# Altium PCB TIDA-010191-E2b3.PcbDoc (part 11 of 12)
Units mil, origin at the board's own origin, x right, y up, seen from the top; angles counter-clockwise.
Board outline 9842.52 x 9842.4 mil, 6 copper layers (Layer 1 - Top Layer, Layer 2 - GND Layer, Layer 3 - Signal, Layer 4 - Signal, Layer 5 - GND, Bottom Layer), stack 59.9 mil thick; 1178 components, 642 nets, 3329 pads, 2967 vias.
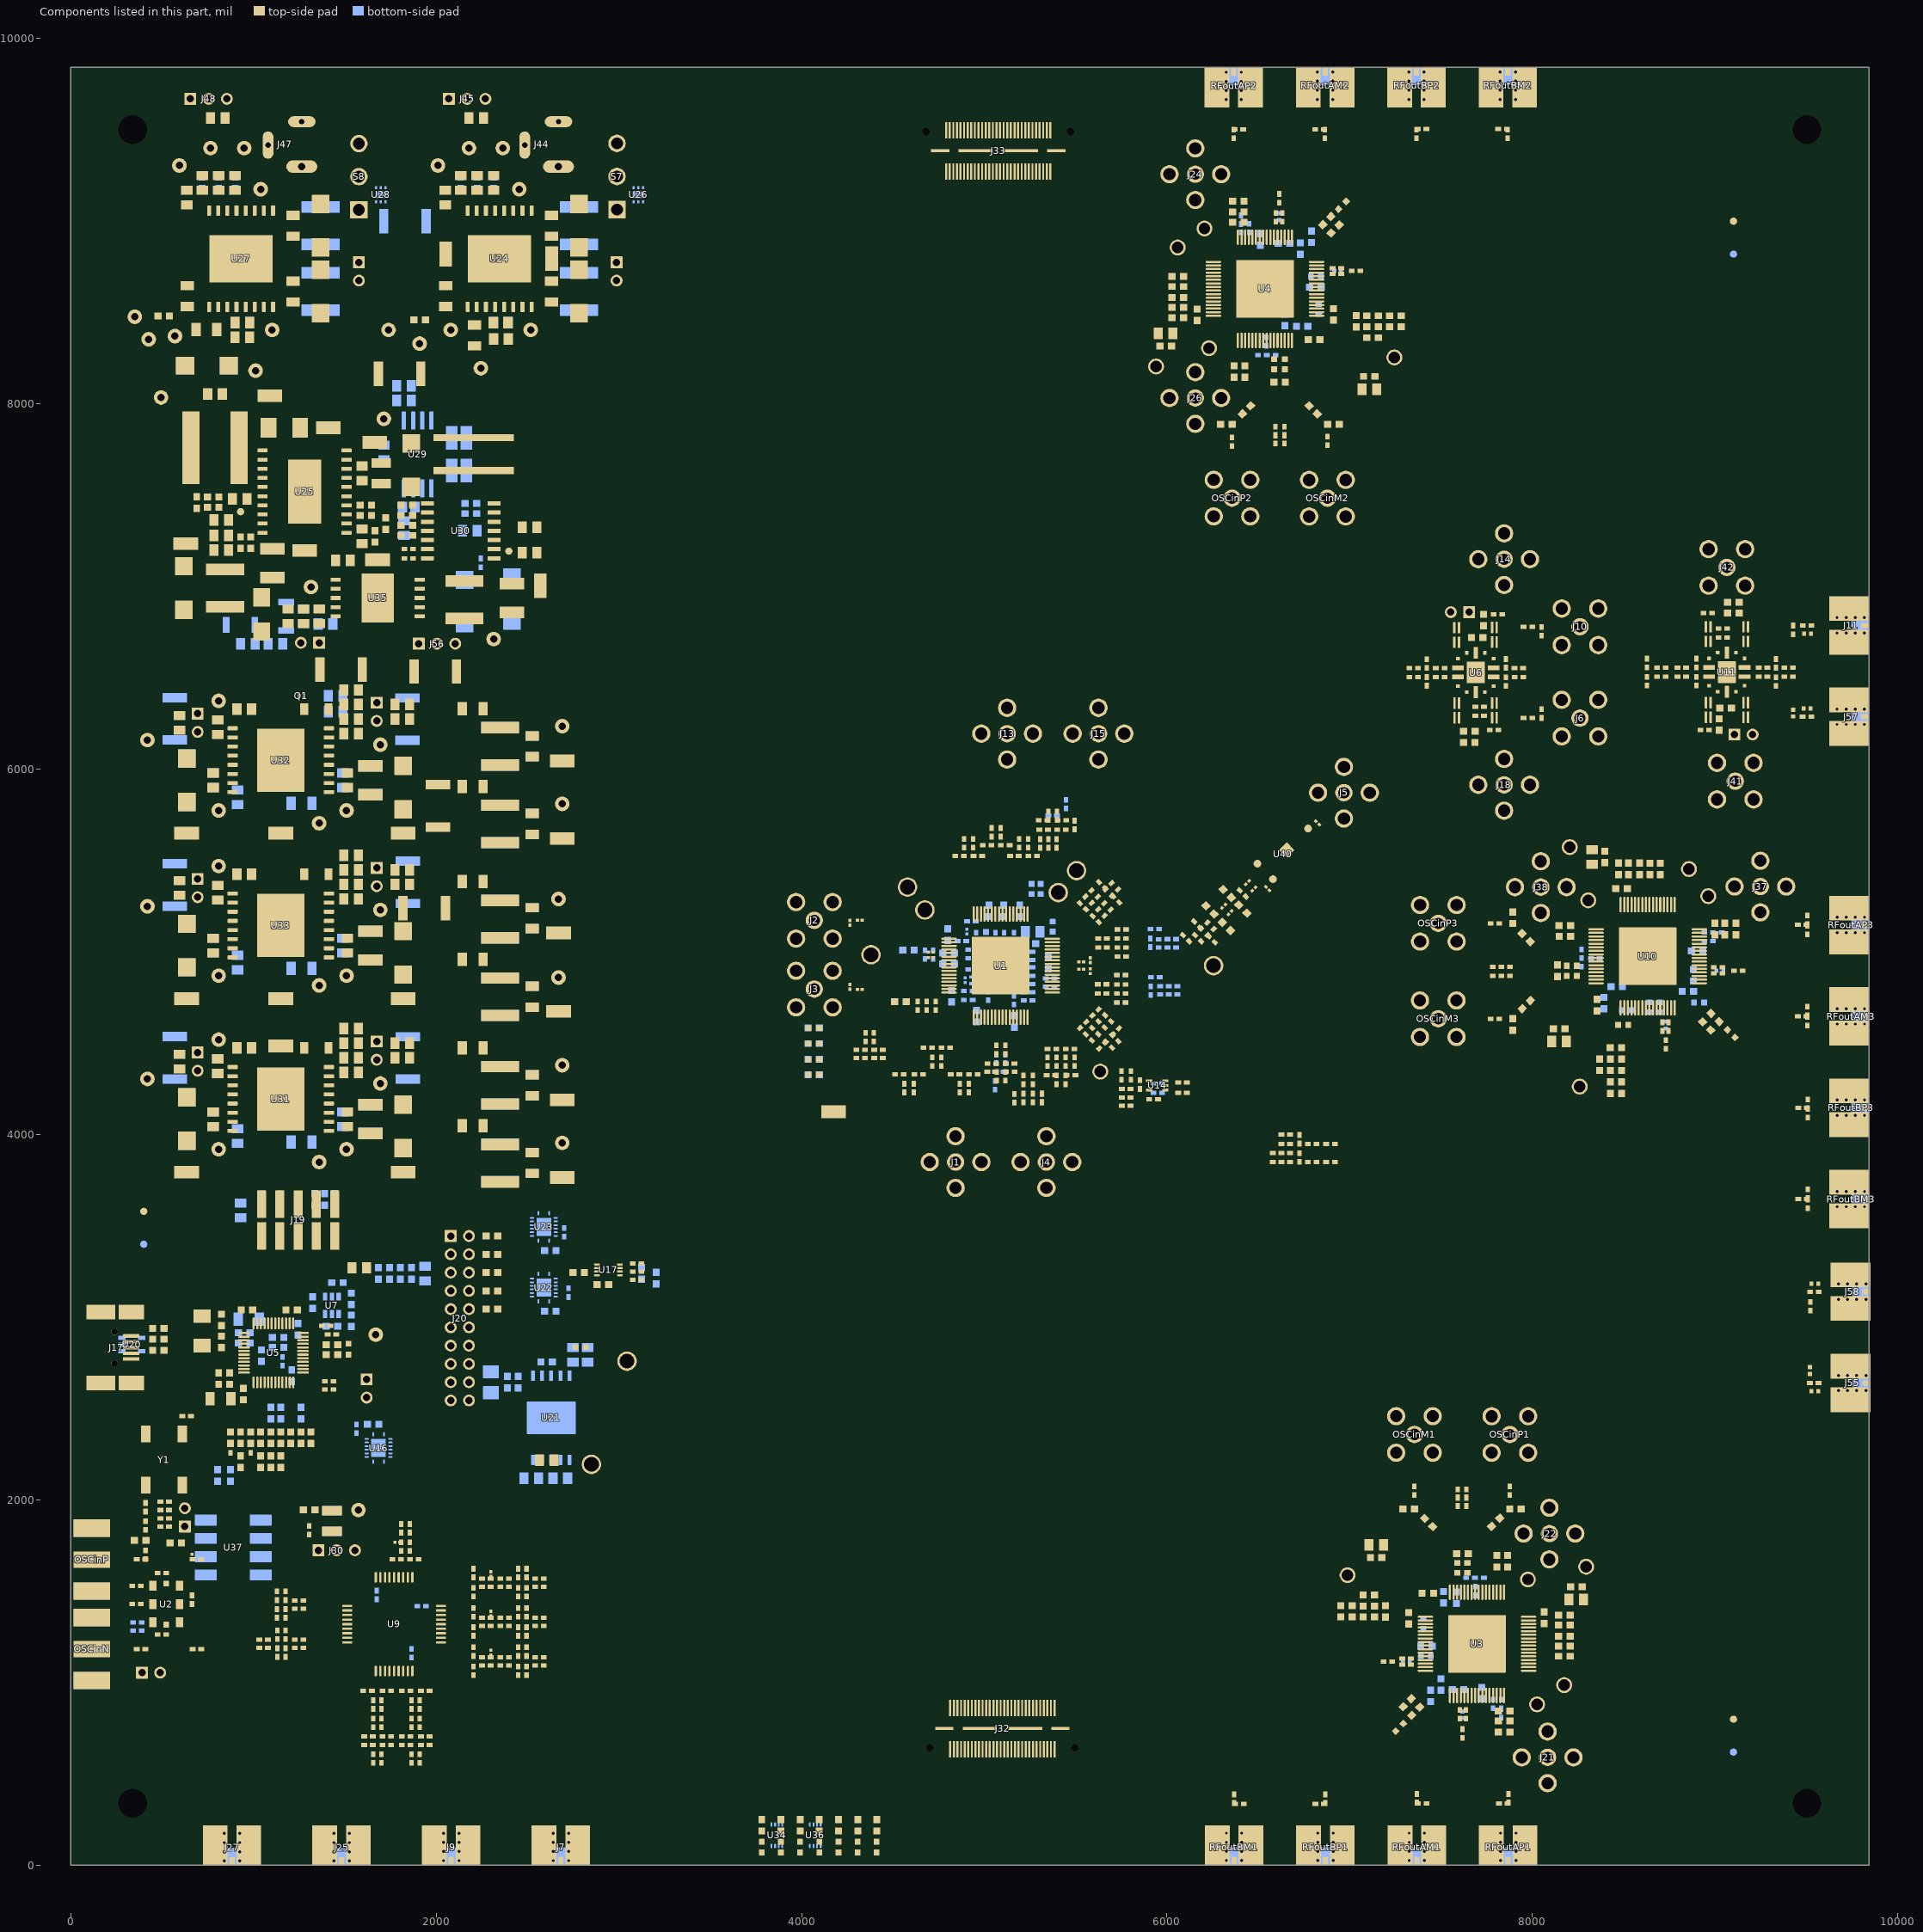
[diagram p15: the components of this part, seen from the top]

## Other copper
Layer 1 - Top Layer:
  region net GND: 7625.94,6467.75 7625.94,6457.75 7580.94,6412.75 7580.94,6233.75 7573.94,6226.75 7538.94,6226.75 7528.94,6236.75 7528.94,6451.75 7544.94,6467.75
  region net P4V5: 7652.94,6455.75 7652.94,6195.75 7643.94,6186.75 7603.94,6186.75 7591.94,6198.75 7591.94,6404.75 7642.94,6455.75
  region net NetC73_2: 7737.94,6604.75 7785.94,6652.75 7785.94,6815.75 7803.94,6833.75 7803.94,6858.75 7771.94,6858.75 7763.94,6850.75 7763.94,6705.75 7726.94,6668.75 7726.94,6604.75
  region net GND: 6211.12,8733.05 6211.12,8784.84 6311.12,8784.84 6321.12,8774.84 6321.12,8739.84 6314.33,8733.05
  region net GND: 6380,8955 6433,8955 6433,8853 6425,8845 6390,8845 6380,8855
  region net GND: 6861,8625 6765,8625 6755,8615 6755,8606 6766,8595 6861,8595
  region net GND: 8021.23,1109.12 8021.23,1058.14 7921.23,1058.14 7911.23,1068.14 7911.23,1103.14 7917.21,1109.12
  region net GND: 8566.43,5301.55 8452.5,5301.55 8305.5,5154.55 8305.5,5060.42 8515.37,5060.42 8566.43,5111.48
  region net GND: 8021.35,1277 8021.35,1390.98 7874.35,1537.98 7778.35,1537.98 7778.35,1329.98 7831.33,1277
  region net GND: 8625,4651.55 8625,4748.05 8615.5,4757.55 8606.5,4757.55 8594.5,4745.55 8594.5,4651.55
  region net GND: 8734.8,5301.43 8780.42,5301.43 8780.42,5196.5 8775.34,5191.43 8740.34,5191.43 8734.8,5196.96
  region net GND: 6211,8565 6211,8452 6358,8305 6452.47,8305 6452.47,8514.53 6402,8565
  region net GND: 960,6370 960,5910 940,5890 855,5890 855,5835 875,5815 875,5730 855,5710 765,5710 745,5730 745,5815 765,5835 855,5835 855,5890 840,5890 815,5915 815,5925 625,5925 565,5865 565,5445 540,5420 540,5360 730,5360 730,5480 780,5530 935,5530 965,5500 965,5010 940,4985 855,4985 855,4930 875,4910 875,4825 855,4805 770,4805 750,4825 750,4910 770,4930 855,4930 855,4985 840,4985 815,5010 815,5020 625,5020 565,4960 565,4495 540,4470 540,4410 730,4410 730,4535 780,4585 925,4585 965,4545 965,4055 945,4035 855,4035 855,3980 875,3960 875,3880 855,3860 765,3860 745,3880 745,3960 763.57,3980 855,3980 855,4035 835,4035 815,4055 815,4070 625,4070 565,4010 565,3749 1895,3749 1895,3980 1770,3980 1680,4070 1480,4070 1480,4015 1495,4000 1540,4000 1595,3945 1595,3875 1515,3795 1328.6,3795 1300,3823.6 1300,4530 1405,4635 1730,4635 1830,4535 1830,4465 1905,4465 1905,4980 1865,5020 1480,5020 1480,4965 1495,4950 1540,4950 1595,4895 1595,4835 1505,4745 1325,4745 1300,4770 1300,5475 1410,5585 1730,5585 1830,5485 1830,5415 1905,5415 1905,5815 1885,5835 1770,5835 1675,5930 1480,5930 1480,5875 1500,5855 1545,5855 1600,5800 1600,5740 1509.53,5649.53 1325.47,5649.53 1300,5675 1300,6370 1257,6370 1257,6420 960,6420
  region net GND: 1986.56,8620 2851.56,8620 2871.56,8640 2871.56,8925 2851.56,8945 1986.56,8945
  region net GND: 560,7315 810,7315 820,7305 820,7165 835,7150 945,7150 965,7170 965,7230 970,7235 1015,7235 1045,7265 1140,7265 1185,7310 1185,7915 1115,7985 820,7985 800,8005 800,8090 810,8100 810,8260 825,8275 940,8275 955,8260 955,8135 980,8110 1140,8110 1300,7950 1555,7950 1665,7840 1910,7840 1935,7815 1935,7735 1925,7725 1830,7725 1735,7630 1460,7630 1375,7545 1375,7340 1405,7310 1535,7310 1540,7305 1540,7285 1530,7275 1475,7275 1340,7140 1060,7140 950,7030 575,7030 545,7060 545,7300
  region net GND: 1500,7170 1510,7180 1545,7180 1560,7195 1560,7257 1568,7265 1695,7265 1755,7205 1755,7135 1780,7110 2345,7110 2360,7125 2555,7125 2605,7075 2605,6935 2595,6925 2145,6925 2080,6990 2055,6990 2020,7025 1845,7025 1805,6985 1805,6870 1945,6730 1945,6655 1925,6635 1605,6635 1580,6660 1580,7030 1500,7110
  region net P5V0: 2460,7480 2523,7417 2523,7151 2532,7142 2578,7142 2640,7080 2640,6940 2600,6900 2140,6900 2075,6965 2050,6965 2015,7000 1875,7000 1860,6985 1860,6890 1875,6875 1940,6875 2065,6750 2065,6485 2100,6450 2750,6450 3000,6700 3000,8440 2855,8585 2385,8585 2360,8560 2360,8175 2300,8115 2200,8115 2080,8235 1885,8235 1835,8185 1835,7940 1915,7860 2025,7750 2410,7750 2460,7700
  region net GND: 634.91,8448 634.91,8368 709.91,8368 709.91,8448
  region net P3V8: 515,7240 515,7530 540,7555 760,7555 780,7575 780,8082 688.5,8173.5 688.5,8247.5 676,8260 610,8260 123,8260 30,8167 30,4200 130,4100 915,4100 935,4120 935,4265 915,4285 570,4285 515,4340 515,4980 585,5050 915,5050 935,5070 935,5215 915,5235 575,5235 515,5295 515,5875 590,5950 915,5950 935,5970 935,6120 915,6140 580,6140 515,6205
  region net NetC156_2: 9118.5,4909.55 9038.5,4909.55 9038.5,4885.55 9118.5,4885.55
  region net GND: 460,2315 460,2410 365,2410 365,2315
  region net NetJ8_1: 585,1880 595,1890 655,1890 665,1880 665,1770 630,1735 595,1735 585,1745
  region net NetC19_2: 520,2105 550,2135 630,2135 660,2105 660,2060 570,1970 570,1745 560,1735 530,1735 520,1745
  region net GND: 5356,9228 5356,9318 5358,9320 5385,9320 5390,9315 5390,9250 5368,9228
  region net GND: 15,940 220,940 220,1080 15,1080
  region net GND: 15,1775.19 220,1775.19 220,1915.19 15,1915.19
  region net GND: 15,1285 220,1285 220,1570 15,1570
  region net GND: 7115,8170 7175,8170 7195,8150 7195,8045 7115,8045
  region net GND: 8391,4822 8293,4822 8276,4839 8276,4849 8282,4855 8387,4855 8391,4851
  region net NetC61_1: 7217.2,1104.31 7297.2,1104.31 7297.2,1128.31 7217.2,1128.31
  region net +3.3VLMK: 4480.61,4652.52 4480.61,4742.52 4490.61,4752.52 4525.61,4752.52 4535.61,4742.52 4535.61,4652.52
  region net GND: 5495.74,765 4705.74,765 4705.74,735 5495.74,735
  region net GND: 4105,4185 4245,4185 4245,4065 4105,4065
  region net NetC173_2: 8741.81,4502.14 8741.81,4582.14 8717.81,4582.14 8717.81,4502.14
  region net GND: 8138.82,4599.38 8078.82,4599.38 8058.82,4579.38 8058.82,4474.38 8138.82,4474.38
  region net P3V3_LMX: 8153.18,4599.38 8213.18,4599.38 8233.18,4579.38 8233.18,4474.38 8153.18,4474.38
  region net GND: 8548.5,4651.55 8548.5,4744.55 8535.5,4757.55 8470.5,4757.55 8470.5,4660.55 8479.5,4651.55
  region net GND: 8418.44,5512.61 8418.44,5427.61 8288.44,5427.61 8288.44,5512.61
  region net P3V3_LMX: 8433.56,5528.61 8443.56,5518.61 8443.56,5468.61 8448.56,5463.61 8488.56,5463.61 8493.56,5468.61 8493.56,5563.61 8438.56,5618.61 8178.56,5618.61 8158.56,5598.61 8158.56,5548.61 8178.56,5528.61
  region net GND: 8955.5,5132.55 8955.5,5081.05 8852,5081.05 8845.5,5087.55 8845.5,5122.55 8855.5,5132.55
  region net GND: 4819.93,816.65 4819.93,924.39 4810.67,933.65 4796.93,933.65 4787.93,924.65 4787.93,816.65
  region net GND: 5378.32,682 5378.32,574.26 5387.58,565 5401.32,565 5410.32,574 5410.32,682
  region net GND: 5253,682 5253,574.26 5243.74,565 5230,565 5221,574 5221,682
  region net GND: 5331.74,682 5331.74,574.26 5322.48,565 5308.74,565 5299.74,574 5299.74,682
  region net GND: 5174.26,682 5174.26,574.26 5165,565 5151.26,565 5142.26,574 5142.26,682
  region net GND: 5095.52,682 5095.52,574.26 5086.26,565 5072.52,565 5063.52,574 5063.52,682
  region net GND: 5016.78,682 5016.78,574.26 5007.52,565 4993.78,565 4984.78,574 4984.78,682
  region net GND: 4938.04,682 4938.04,574.26 4928.78,565 4915.04,565 4906.04,574 4906.04,682
  region net GND: 4859.3,682 4859.3,574.26 4850.04,565 4836.3,565 4827.3,574 4827.3,682
  region net GND: 5338.95,816.65 5338.95,924.39 5348.21,933.65 5361.95,933.65 5370.95,924.65 5370.95,816.65
  region net GND: 5260.21,816.65 5260.21,924.39 5269.47,933.65 5283.21,933.65 5292.21,924.65 5292.21,816.65
  region net GND: 5181.47,816.65 5181.47,924.39 5190.73,933.65 5204.47,933.65 5213.47,924.65 5213.47,816.65
  region net GND: 5102.73,816.65 5102.73,924.39 5111.99,933.65 5125.73,933.65 5134.73,924.65 5134.73,816.65
  region net GND: 5023.99,816.65 5023.99,924.39 5033.25,933.65 5046.99,933.65 5055.99,924.65 5055.99,816.65
  region net GND: 4945.25,816.65 4945.25,924.39 4954.51,933.65 4968.25,933.65 4977.25,924.65 4977.25,816.65
  region net GND: 4866.51,816.65 4866.51,924.39 4875.77,933.65 4889.51,933.65 4898.51,924.65 4898.51,816.65
  region net GND: 7371.35,1218 7467.37,1218 7477.35,1227.98 7477.35,1236.98 7466.33,1248 7371.35,1248
  region net GND: 7371.35,1294.98 7464.35,1294.98 7477.35,1307.98 7477.35,1372.98 7380.35,1372.98 7371.35,1363.98
  region net GND: 7137.82,1665.62 7077.82,1665.62 7057.82,1685.62 7057.82,1790.62 7137.82,1790.62
  region net P3V3_LMX: 7152.18,1665.62 7212.18,1665.62 7232.18,1685.62 7232.18,1790.62 7152.18,1790.62
  region net NetC45_1: 7628,730 7628,810 7604,810 7604,730
  region net GND: 7574.35,1452.98 7574.35,1550.98 7567.35,1557.98 7549.35,1557.98 7542.35,1550.98 7542.35,1452.98
  region net GND: 8232.61,1547.44 8147.61,1547.44 8147.61,1417.44 8232.61,1417.44
  region net P3V3_LMX: 8248.61,1407.44 8238.61,1397.44 8188.61,1397.44 8183.61,1392.44 8183.61,1352.44 8188.61,1347.44 8283.61,1347.44 8338.61,1402.44 8338.61,1662.44 8318.61,1682.44 8268.61,1682.44 8248.61,1662.44
  region net GND: 7852.35,887.98 7800,887.98 7800,990.63 7807.35,997.98 7842.35,997.98 7852.35,987.98
  region net P3V3_LMX: 7100,8170 7040,8170 7020,8150 7020,8045 7100,8045
  region net GND: 6861,8548 6768,8548 6755,8535 6755,8470 6852,8470 6861,8479
  region net NetC189_2: 7027.26,8739.4 6947.26,8739.4 6947.26,8715.4 7027.26,8715.4
  region net P3V3_LMX: 5985,8435 5995,8445 6045,8445 6050,8450 6050,8490 6045,8495 5950,8495 5895,8440 5895,8180 5915,8160 5965,8160 5985,8180
  region net GND: 6000,8295 6085,8295 6085,8425 6000,8425
  region net GND: 6658,8390 6658,8292 6665,8285 6683,8285 6690,8292 6690,8390
  region net +3.3V_CDCM7005: 1270,1895 1295,1920 1295,1965 1270,1990 1185,1990 1170,1975 1170,1910 1185,1895
  region net GND: 1350,1875 1350,1820 1370,1800 1500,1800 1520,1820 1520,1875
  region net C_VCC: 1315,1920 1340,1895 1590,1895 1615,1920 1615,1965 1590,1990 1340,1990 1315,1965
  region net C_VCC: 1838.15,1034.96 1838.15,1103.96 1855.15,1120.96 1870.15,1120.96 1880.15,1110.96 1880.15,1039.96 1875.15,1034.96
  region net C_VCC: 1702,1606 1702,1537 1685,1520 1670,1520 1660,1530 1660,1601 1665,1606
  region net NetC131_2: 6603,9118 6603,9038 6627,9038 6627,9118
  region net NetC75_1: 7726.94,6455.75 7736.94,6455.75 7786.94,6405.75 7786.94,6194.75 7778.94,6186.75 7753.94,6186.75 7743.94,6196.75 7743.94,6226.75 7763.94,6246.75 7763.94,6352.75 7739.94,6376.75 7726.94,6389.75
  region net GND: 7796.94,6194.75 7796.94,6394.75 7803.94,6401.75 7828.94,6401.75 7838.94,6391.75 7838.94,6191.75 7833.94,6186.75 7803.94,6186.75 7796.94,6193.75
  region net P4V5: 7652.94,6604.75 7641.94,6604.75 7591.94,6654.75 7591.94,6813.75 7578.94,6826.75 7533.94,6826.75 7513.94,6846.75 7513.94,6891.75 7528.94,6906.75 7583.94,6906.75 7598.94,6891.75 7598.94,6836.75 7628.94,6806.75 7628.94,6694.75 7652.94,6670.75
  region net GND: 7805.94,6656.75 7796.94,6665.75 7796.94,6807.75 7816.94,6827.75 7816.94,6859.75 7823.94,6866.75 7848.94,6866.75 7853.94,6861.75 7853.94,6666.75 7843.94,6656.75
  region net GND: 7625.94,6592.25 7625.94,6602.25 7580.94,6647.25 7580.94,6807.75 7576.94,6811.75 7543.94,6811.75 7528.94,6796.75 7528.94,6608.25 7544.94,6592.25
  region net GND: 85,2985 105,2965 365,2965 380,2980 478,2980 478,3047 415,3110 105,3110 85,3090
  region net GND: 80,2680 105,2705 259,2705 275,2721 275,2773 284,2782 398,2782 415,2765 415,2590 400,2575 105,2575 80,2600
  region net GND: 1173,2677 1173,2600 1183,2590 1195,2590 1205,2600 1205,2677
  region net GND: 1302,2888 1306,2892 1306,2940 1300,2946 1264,2946 1238,2920 1238,2892 1242,2888
  region net NetJ17_1: 287,2888 378,2888 410,2920 470,2920 470,2960 390,2960 360,2930 298,2930 287,2919
  region net GND: 4804.63,9318.35 4804.63,9210.61 4813.89,9201.35 4827.63,9201.35 4836.63,9210.35 4836.63,9318.35
  region net GND: 4883.37,9318.35 4883.37,9210.61 4892.63,9201.35 4906.37,9201.35 4915.37,9210.35 4915.37,9318.35
  region net GND: 4962.11,9318.35 4962.11,9210.61 4971.37,9201.35 4985.11,9201.35 4994.11,9210.35 4994.11,9318.35
  region net GND: 5040.85,9318.35 5040.85,9210.61 5050.11,9201.35 5063.85,9201.35 5072.85,9210.35 5072.85,9318.35
  region net GND: 5119.59,9318.35 5119.59,9210.61 5128.85,9201.35 5142.59,9201.35 5151.59,9210.35 5151.59,9318.35
  region net GND: 5198.33,9318.35 5198.33,9210.61 5207.59,9201.35 5221.33,9201.35 5230.33,9210.35 5230.33,9318.35
  region net GND: 5277.07,9318.35 5277.07,9210.61 5286.33,9201.35 5300.07,9201.35 5309.07,9210.35 5309.07,9318.35
  region net GND: 4797.42,9453 4797.42,9560.74 4788.16,9570 4774.42,9570 4765.42,9561 4765.42,9453
  region net GND: 4680,9370 5470,9370 5470,9400 4680,9400
  region net GND: 5316.44,9453 5316.44,9560.74 5325.7,9570 5339.44,9570 5348.44,9561 5348.44,9453
  region net GND: 5237.7,9453 5237.7,9560.74 5246.96,9570 5260.7,9570 5269.7,9561 5269.7,9453
  region net GND: 5158.96,9453 5158.96,9560.74 5168.22,9570 5181.96,9570 5190.96,9561 5190.96,9453
  region net GND: 5080.22,9453 5080.22,9560.74 5089.48,9570 5103.22,9570 5112.22,9561 5112.22,9453
  region net GND: 5001.48,9453 5001.48,9560.74 5010.74,9570 5024.48,9570 5033.48,9561 5033.48,9453
  region net GND: 4844,9453 4844,9560.74 4853.26,9570 4867,9570 4876,9561 4876,9453
  region net GND: 4922.74,9453 4922.74,9560.74 4932,9570 4945.74,9570 4954.74,9561 4954.74,9453
  region net VREGIN: 1153,3000 1153,2919 1162,2910 1176,2910 1185,2919 1185,3000
  region net GND: 1114,2934 1114,3014 1160,3060 1200,3060 1200,3020 1160,3020 1145,3005 1145,2934
  region net GND: 995,3000 995,2907 1002,2900 1021,2900 1028,2907 1028,3000
  region net GND: 920,2763 997,2763 1010,2750 1010,2723 998,2711 916,2711 916,2759
  region net GND: 9128,6469.5 9128,6459.5 9173,6414.5 9173,6254 9177,6250 9210,6250 9225,6265 9225,6453.5 9209,6469.5
  region net GND: 9128,6594 9128,6604 9173,6649 9173,6828 9180,6835 9215,6835 9225,6825 9225,6610 9209,6594
  region net GND: 8948,6405 8957,6396 8957,6254 8937,6234 8937,6202 8930,6195 8905,6195 8900,6200 8900,6395 8910,6405
  region net GND: 8957,6867 8957,6667 8950,6660 8925,6660 8915,6670 8915,6870 8920,6875 8950,6875 8957,6868
  region net NetC210_1: 9027,6606 9017,6606 8967,6656 8967,6867 8975,6875 9000,6875 9010,6865 9010,6835 8990,6815 8990,6709 9014,6685 9027,6672
  region net NetC208_2: 9016,6457 8968,6409 8968,6246 8950,6228 8950,6203 8982,6203 8990,6211 8990,6356 9027,6393 9027,6457
  region net P4V5: 9101,6457 9112,6457 9162,6407 9162,6248 9175,6235 9220,6235 9240,6215 9240,6170 9225,6155 9170,6155 9155,6170 9155,6225 9125,6255 9125,6367 9101,6391
  region net P4V5: 9101,6606 9101,6866 9110,6875 9150,6875 9162,6863 9162,6657 9111,6606
  region net GND: 630,6265 540,6265 540,6325 630,6325
  region net P3V3A: 1370,4270.47 1385,4285.47 1605,4285.47 1680,4360.47 1890,4360.47 1920,4390.47 1920,4495.47 1940,4515.47 2170,4515.47 2190,4495.47 2190,4030.47 2170,4010.47 1785,4010.47 1700,4095.47 1385,4095.47 1370,4110.47
  region net GND: 2230,3684.21 2210,3704.21 2210,3804.21 2230,3824.21 2745,3824.21 2765,3804.21 2765,3704.21 2745,3684.21
  region net GND: 2230,4109.21 2210,4129.21 2210,4229.21 2230,4249.21 2745,4249.21 2765,4229.21 2765,4129.21 2745,4109.21
  region net VDDD33: 2210,4067.24 2230,4087.24 2745,4087.24 2765,4067.24 2765,3892.24 2745,3872.24 2235,3872.24 2210,3897.24
  region net +3.3VLMK: 2210,4494.21 2230,4514.21 2745,4514.21 2765,4494.21 2765,4319.21 2745,4299.21 2235,4299.21 2210,4324.21
  region net GND: 2230,4594.21 2210,4614.21 2210,4714.21 2230,4734.21 2745,4734.21 2765,4714.21 2765,4614.21 2745,4594.21
  region net GND: 2230,5019.21 2210,5039.21 2210,5139.21 2230,5159.21 2745,5159.21 2765,5139.21 2765,5039.21 2745,5019.21
  region net +3.3V_CDCM7005: 2210,4979.21 2230,4999.21 2745,4999.21 2765,4979.21 2765,4804.21 2745,4784.21 2235,4784.21 2210,4809.21
  region net +3.3V_VCO: 2210,5404.21 2230,5424.21 2745,5424.21 2765,5404.21 2765,5229.21 2745,5209.21 2235,5209.21 2210,5234.21
  region net NetL28_1: 2170,5730 2190,5710 2190,4935 2170,4915 1985,4915 1965,4935 1965,5300 1925,5340 1925,5710 1945,5730
  region net P3V3C: 1370,5220.47 1385,5235.47 1605,5235.47 1680,5310.47 1924.53,5310.47 1945,5290 1945,5065 1925.47,5045.47 1700,5045.47 1385,5045.47 1370,5060.47
  region net GND: 2230,5540 2210,5560 2210,5660 2230,5680 2745,5680 2765,5660 2765,5560 2745,5540
  region net GND: 2230,5965 2210,5985 2210,6085 2230,6105 2745,6105 2765,6085 2765,5985 2745,5965
  region net +3.3V_LMXRF: 2210,5925 2230,5945 2745,5945 2765,5925 2765,5750 2745,5730 2235,5730 2210,5755
  region net P3V3_LMX: 2210,6350 2230,6370 2745,6370 2765,6350 2765,6165 2745,6145 2230,6145 2210,6165
  region net P3V3B: 1370,6125 1385,6140 1605,6140 1680,6215 1890,6215 1920,6245 1920,6350 1940,6370 2170,6370 2190,6350 2190,5885 2170,5865 1785,5865 1700,5950 1385,5950 1370,5965
  region net NetR545_1: 1561.01,6478.18 1618.91,6478.36 1629.19,6467.02 1906.89,6467.02 1925,6485.13 1925,6585 1897.77,6612.23 1568.35,6612.23 1550,6593.89 1550,6489.2
  region net P4V5: 545,6970 575,7000 955,7000 1065,7110 1345,7110 1415,7180 1470,7180 1480,7170 1480,7090 1500,7070 1500,6945 1480,6925 1240,6925 1225,6910 1225,6850 1220,6845 1000,6845 955,6800 880,6800 845,6765 845,6670 901.6,6613.4 1386.6,6613.4 1415,6585 1415,6475 1390,6450 745,6450 545,6650 545,6830
  region net NetD12_1: 825,7915 870,7960 1095,7960 1140,7915 1140,7575 1095,7530 870,7530 825,7575
  region net GND: 2170,8270 2250,8270 2250,8345 2170,8345
  region net P5V0*: 2405,7700 2430,7675 2430,7520 2405,7495 1740,7495 1725,7480 1475,7480 1455,7500 1455,7595 1475,7615 1750,7615 1835,7700
  region net NetC250_1: 1610,8585 1650,8545 1650,8350 1715,8285 1715,8090 1675,8050 1230,8050 945,8335 945,8560 970,8585
  region net GND: 575,8620 1440,8620 1460,8640 1460,8925 1440,8945 575,8945
  region net GND: 932,9225 778,9225 778,9278 785,9285 785,9330 932,9330
  region net GND: 685,9225 752,9225 752,9278 745,9285 745,9330 685,9330
  region net VIN_P5V0_Redundant: 600,9115 600,9020 610,9010 660,9010 670,9020 670,9115
  region net VIN_P5V0_Redundant: 820,9530 918.31,9530 930,9541.69 930,9588.31 918.31,9600 820,9600
  region net NetJ47_1: 1175,9230 1215,9190 1605,9190 1645,9230 1645,9320 1605,9360 1215,9360 1175,9320
  region net VIN_P5V0_Redundant: 1640,9115 1595,9160 1190,9160 1120,9230 1015,9230 945,9160 945,9015 985,8975 1450,8975 1485,8940 1485,8780 1525,8740 1735,8740 1775,8780 1775,9075 1735,9115
  region net VIN_P5V0: 2235,9530 2333.31,9530 2345,9541.69 2345,9588.31 2333.31,9600 2235,9600
  region net VIN_P5V0: 2015,9115 2015,9020 2025,9010 2075,9010 2085,9020 2085,9115
  region net GND: 2347,9225 2193,9225 2193,9278 2200,9285 2200,9330 2347,9330
  region net GND: 2100,9225 2167,9225 2167,9278 2160,9285 2160,9330 2100,9330
  region net VIN_P5V0: 3055,9115 3010,9160 2605,9160 2535,9230 2430,9230 2360,9160 2360,9015 2400,8975 2865,8975 2900,8940 2900,8780 2940,8740 3150,8740 3190,8780 3190,9075 3150,9115
  region net NetJ44_1: 2580,9230 2620,9190 3010,9190 3050,9230 3050,9320 3010,9360 2620,9360 2580,9320
  text "TOP LAYER" at -232.05,-1884.88 h60
Layer 2 - GND Layer:
  pour cut-out: 420,1285 620,1285 620,1575 425,1575 420,1570
  text "GND Layer" at -204.91,-1899.88 h60
Layer 4 - Signal:
  pour cut-out: 420,1285 620,1285 620,1575 425,1575 420,1570
  text "Signal Layer2" at -214.91,-1899.88 h60
Layer 3 - Signal:
  text "Signal Layer1" at -224.91,-1889.88 h60
Layer 5 - GND:
  text "PWR Layer" at -194.91,-1889.88 h60
Bottom Layer:
  region net GND: 962.03,4145.47 1022,4082.59 1022,4020.47 1298,4020.47 1298,4536.14 962.03,4536.14
  region net GND: 962.03,5095.47 1022,5032.59 1022,4970.47 1298,4970.47 1298,5507.97 962.03,5507.97
  region net GND: 962.03,6000 1022,5937.12 1022,5875 1298,5875 1298,6418.21 962.03,6418.21
  region net P3V3C: 1455,5045.47 1926.26,5045.47 1946,5065.21 1946,5300.47 1590,5300.47 1455,5165.47
  region net P3V8: 552,8143 552,8271 689,8271 689,8143
  region net GND: 940,8272 940,8149 803,8149 803,8272
  region net GND: 973.07,5834.85 973.07,5781.62 966.3,5774.85 881.3,5774.85 881.3,5834.85
  region net GND: 973.18,4930.32 973.18,4877.2 966.3,4870.32 881.3,4870.32 881.3,4930.32
  region net GND: 973.6,3980.32 973.6,3927.63 927.94,3881.97 881.3,3881.97 881.3,3980.32
  region net GND: 15,940 220,940 220,1080 15,1080
  region net GND: 15,1775.19 220,1775.19 220,1915.19 15,1915.19
  region net GND: 15,1285 220,1285 220,1570 15,1570
  region net GND: 565,3753.46 705.11,3753.46 705,3905.47 795,3995.47 854.55,3995.47 854.55,4023.64 812.61,4070.47 625,4070.47 565,4010.47
  region net GND: 1550,3995.47 1575,3970.47 1710,3970.47 1710,4040.47 1690,4060.47 1550,4060.47
  region net GND: 1550,4945.47 1575,4920.47 1710,4920.47 1710,4990.47 1690,5010.47 1550,5010.47
  region net GND: 565,4855.47 705,4855.47 795,4945.47 820,4945.47 820,5015.47 815,5020.47 625,5020.47 565,4960.47
  region net GND: 1550,5850 1647.66,5700.79 1905,5700.79 1905,5915 1550,5915
  region net GND: 565,5760 705,5760 795,5850 820,5850 820,5920 815,5925 625,5925 565,5865
  region net GND: 2055,7080 2055,7015 2125,6945 2530,6945 2530,7080 2485,7125 2100,7125
  region net GND: 1170,8930 1475,8930 1475,8660 1170,8660
  region net GND: 2585,8930 2890,8930 2890,8660 2585,8660
  region net GND: 5235.5,5018.95 5241.59,5025.04 5241.59,5066.29 5245.26,5069.85 5260,5084.59 5260,5139.99 5256.09,5144 5198.84,5144 5194.17,5139.33 5194.17,5088.72 5186.39,5081.38 4928.37,5081.38 4920.51,5089.24 4920.51,5103.03 4916.04,5107.5 4889.1,5107.5 4884.82,5103.22 4884.82,5048.07 4887.85,5045 4932.03,5045 4944.28,5032.75 4944.28,4815.82 4936.5,4808.04 4924.24,4808.04 4924.24,4807.43 4920.26,4803.45 4920.26,4791.8 4920.26,4771.08 4920.06,4725.24 4924.55,4720.75 4952.32,4720.75 4961.3,4729.74 4961.3,4759.34 4966.2,4765 5040,4765 5062.09,4742.91 5179.98,4742.91 5191.48,4731.62 5191.48,4730 5199.77,4721.71 5231.04,4721.71 5235.5,4726.17 5235.5,4760.5
  region net GND: 8621,4705 8601,4725 8601,4755 8606,4760 8641,4760 8661,4740 8661,4710 8656,4705
  region net GND: 1350,1875 1350,1820 1370,1800 1500,1800 1520,1820 1520,1875
  region net C_VCC: 1350,1895 1350,1950 1370,1970 1500,1970 1520,1950 1520,1895
  region net GND: 7480,1188.33 7471.54,1179.87 7431.54,1179.87 7426.54,1184.87 7426.54,1219.87 7451.67,1245 7470,1245 7480,1235
  region net GND: 6755,8655 6760,8660 6800,8660 6805,8655 6805,8620 6785,8600 6760,8600 6755,8605
  region net P5V0: 2675,8570 2870,8570 2890,8550 2890,8475 2675,8475
  region net GND: 1645,3215 1660,3230 1980,3230 1995,3215 1995,3180 1980,3165 1660,3165 1645,3180
  region net GND: 2265,2635 2250,2620 2250,2545 2265,2530 2420,2530 2470,2580 2470,2635
  region net VREGIN: 2545,2655 2540,2650 2265,2650 2255,2660 2255,2750 2265,2760 2490,2760 2545,2705
  region net VDDD33: 1635,3240 1645,3250 1970,3250 1980,3260 1980,3350 1970,3360 1610,3360 1570,3320 1570,3260 1590,3240
  region net P3V3A: 1455,4095.47 1815,4095.47 1915,4195.47 1915,4350.47 1590,4350.47 1455,4215.47
  region net NetR502_1: 705,4508.98 779.53,4583.5 1700.47,4583.5 1775,4508.98 1915,4508.98 1925,4518.98 1925,4623.98 1801.98,4747 633.02,4747 480,4593.98 480,4528.98 500,4508.98
  region net P3V8: 360,4365.47 605,4365.47 670,4300 735,4300 755,4320 755,4345 775,4365.47 835,4365.47 855,4345 855,4095.47 845,4095.47 815,4095.47 520,4095.47 360,4255.47
  region net P3V8: 360,5315.47 605,5315.47 815,5105.47 815,5045.47 520,5045.47 360,5205.47
  region net NetR526_1: 705,5455.47 779.53,5530 1700.47,5530 1775,5455.47 1915,5455.47 1925,5465.47 1925,5570.47 1845.95,5649.53 589.05,5649.53 480,5540.47 480,5475.47 500,5455.47
  region net GND: 2570,3815.79 2570,3685.79 2235,3685.79 2235,3815.79
  region net GND: 2570,4240.79 2570,4110.79 2235,4110.79 2235,4240.79
  region net VDDD33: 2570,3872.24 2570,4002.24 2235,4002.24 2235,3872.24
  region net +3.3VLMK: 2570,4299.21 2570,4429.21 2235,4429.21 2235,4299.21
  region net +3.3V_CDCM7005: 2570,4784.21 2570,4914.21 2235,4914.21 2235,4784.21
  region net +3.3V_VCO: 2570,5209.21 2570,5339.21 2235,5339.21 2235,5209.21
  region net +3.3V_LMXRF: 2570,5730 2570,5860 2235,5860 2235,5730
  region net P3V3B: 1455,5950 1815,5950 1915,6050 1915,6205 1790,6205 1765,6180 1565,6180 1455,6070
  region net P3V8: 360,6220 605,6220 815,6010 815,5950 520,5950 360,6110
  region net GND: 2570,4725.79 2570,4595.79 2235,4595.79 2235,4725.79
  region net GND: 2570,5150.79 2570,5020.79 2235,5020.79 2235,5150.79
  region net GND: 2570,5671.57 2570,5541.57 2235,5541.57 2235,5671.57
  region net GND: 2570,6096.57 2570,5966.57 2235,5966.57 2235,6096.57
  region net P3V3_LMX: 2570,6155 2570,6285 2235,6285 2235,6155
  region net NetR514_1: 702.5,6368.43 787.5,6453.43 1687.5,6453.43 1772.5,6368.43 1912.5,6368.43 1922.5,6378.43 1922.5,6483.43 1792.5,6613.43 637.5,6613.43 477.5,6453.43 477.5,6388.43 497.5,6368.43
  region net P5V0: 2065,6650 2065,6865 2490,6865 2490,6650
  region net GND: 830,6835 885,6835 965,6755 965,6650 900,6650 830,6720
  region net GND: 2175,7260 2095,7260 2095,7350 2175,7350
  region net GND: 1735,8135 1810,8135 1810,7985 1750,7985 1735,8000
  region net GND: 2120,7805 2120,7645 2050,7645 2050,7805
  region net GND: 685,9220 930,9220 930,9330 685,9330
  region net GND: 1660,9174 1740,9174 1740,9220 1660,9220
  region net GND: 2100,9220 2345,9220 2345,9330 2100,9330
  region net GND: 3070,9174 3150,9174 3150,9220 3070,9220
  region net VIN_P5V0: 3051,9116 3149,9116 3170,9095 3051,9095
  text "BOTTOM LAYER" at -231.28,-1903.37 h60

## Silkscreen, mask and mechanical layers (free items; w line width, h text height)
Top Overlay:
  text "P5V0" at 1060,8279.88 h41.77
  text "P5V0" at 2475,8255 h41.77
  text "P3V8" at 445,8145 h41.77
  text "P4V5" at 1275,7065 h41.77
  text "P5V0" at 2275,6565 h41.77
  text "P3V3_LMK" at 2770,6225 h41.77
  text "P3V3B" at 1775,6085 h41.77
  text "P3V8" at 380,6070 h41.77
  text "+3.3V_LMXRF" at 2770,5805 h41.77
  text "+3.3V_VCO" at 2735,5285 h41.77
  text "P3V3C" at 1515,5180.47 h41.77
  text "P3V8" at 375,5160 h41.77
  text "+3.3V_CDCM7005" at 2740,4855 h41.77
  text "+3.3VLMK" at 2770,4370 h41.77
  text "P3V3A" at 1770,4238.07 h41.77
  text "P3V8" at 380,4215 h41.77
  text "VDDD33" at 2780,3945 h41.77
  text "TOP OVERLAY" at -231.28,-1903.37 h50
Bottom Overlay:
  text "BOTTOM OVERLAY" at -117.05,-1916.88 h50
Top Paste:
  text "TOP PASTE" at -231.28,-1903.37 h60
Bottom Paste:
  text "BOTTOM PASTE" at -231.28,-1903.37 h60
Top Solder:
  text "TOP SOLDER" at -231.28,-1903.37 h60
Bottom Solder:
  text "BOTTOM SOLDER" at -231.28,-1903.37 h60
Drill Guide:
  text ".Layer_Name" at -231.28,-1903.37 h60
M1 Board Outline:
  the board outline again, w10
M2 Board Dimensions:
  rectangle: -683.78,-1455.38 -308.78,-1330.38
  rectangle: -808.78,-1330.38 -683.78,-1205.38
  lines w7: -808.78,-1330.38 191.22,-1330.38 ; -683.78,-1455.38 -683.78,-1205.38 ; -558.78,-1455.38 -558.78,-1205.38 ; -308.78,-1455.38 -308.78,-1205.38 ; -58.78,-1455.38 -58.78,-1205.38 ; -808.78,-1455.38 -808.78,-1205.38 191.22,-1205.38 191.22,-1455.38 -808.78,-1455.38
  lines w10: -808.78,-1520.38 -808.78,-1500.38 ; -748.78,-1530.38 -808.78,-1510.38 ; -748.78,-1490.38 -808.78,-1510.38 ; -584.69,-1510.38 -808.78,-1510.38 ; -32.86,-1510.38 191.22,-1510.38 ; 131.22,-1530.38 191.22,-1510.38 ; 131.22,-1490.38 191.22,-1510.38 ; 191.22,-1520.38 191.22,-1500.38
  text "1000 (mil)" at -574.69,-1546.37 h60
M3 3D STEP Top:
  text ".Layer_Name" at -231.28,-1903.37 h60
M4 3D STEP Bottom:
  text ".Layer_Name" at -231.28,-1903.37 h60
M5 Assembly Top:
  lines w10: -1100.28,-1975.05 5499.73,-1975.05 ; -1100.28,-1771.71 5501.73,-1771.71 ; -1100.28,-1568.38 -1100.28,-2178.38 2904.72,-2178.38 5501.73,-2178.38 5501.73,-1568.38 -1099.78,-1568.38 -1099.78,-2178.38 475.72,-2178.38 ; 1364.72,-2178.38 1364.72,-1568.38 ; 2631.72,-1771.71 2631.72,-1568.38 ; 3471.72,-1771.71 3471.72,-1568.38 ; 4093.72,-2184.88 4093.72,-1982.05
  text "COMPONENTS MARKED 'DNP' SHOULD NOT BE POPULATED." at 345.22,-1363.38 h25
  text "ASSEMBLY VARIANT:" at 344.72,-1478.88 h25
  text ".VariantName" at 1380.72,-1478.88 h25
  text "E3" at 3066.95,-1693.88 h25
  text "PCB VIEWED FROM TOP SIDE" at -1036.78,-1700.55 h25
  text "BOARD #:" at 1439.72,-1700.55 h25
  text "'.PRJ_Number'" at 1985.22,-1700.55 h25
  text "REV:" at 2829.72,-1700.55 h25
  text "SVN REV:" at 3667.72,-1700.55 h25
  text "010131" at 1760.82,-1895.68 h25
  text "ASSEMBLY TOP" at -225.05,-1897.88 h25
  text "TID #:" at 1421.99,-1901.01 h25
  text "IGNORE ->" at -1036.78,-1903.37 h25
  text "PLOT NAME =" at -1036.78,-2109.22 h25
  text ".plot_File_Name" at -231.28,-2109.22 h25
  text "GENERATED    :" at 1441.72,-2109.22 h25
  text "'.Print_Date'" at 2311.22,-2109.22 h25
  text "'.Print_Time'" at 3040.22,-2109.22 h25
  text "TEXAS INSTRUMENTS" at 4304.73,-2109.22 h25
M6 Assembly Bottom:
  lines w10: -1100.78,-1772.21 5501.23,-1772.21 ; -1098.78,-1975.55 5501.23,-1975.55 ; 307.22,-2185.38 307.22,-1982.55 ; 929.22,-1772.21 929.22,-1568.88 ; 1769.22,-1772.21 1769.22,-1568.88 ; 3036.22,-2178.88 3036.22,-1568.88 ; 3925.22,-2178.88 5500.73,-2178.88 5500.73,-1568.88 -1100.78,-1568.88 -1100.78,-2178.88 1496.22,-2178.88 5501.23,-2178.88 5501.23,-1568.88
  text "COMPONENTS MARKED 'DNP' SHOULD NOT BE POPULATED." at 5293.73,-1362.88 h25
  text ".VariantName" at 4249.73,-1478.88 h25
  text "ASSEMBLY VARIANT:" at 5288.73,-1478.88 h25
  text "E3" at 1297.33,-1687.02 h25
  text "SVN REV:" at 733.22,-1701.05 h25
  text "REV:" at 1571.22,-1701.05 h25
  text "'.PRJ_Number'" at 2415.72,-1701.05 h25
  text "BOARD #:" at 2961.22,-1701.05 h25
  text "PCB VIEWED FROM BOTTOM SIDE" at 5437.73,-1701.05 h25
  text "ASSEMBLY BOTTOM" at 4320.79,-1890.16 h25
  text "010131" at 2635.54,-1893.09 h25
  text "TID #:" at 2974.38,-1898.42 h25
  text "IGNORE ->" at 1739.58,-1903.37 h25
  text "LAYER NAME =" at 5365.03,-1902.51 h25
  text "TEXAS INSTRUMENTS" at 96.22,-2109.72 h25
  text "'.Print_Time'" at 1360.72,-2109.72 h25
  text "'.Print_Date'" at 2089.72,-2109.72 h25
  text "GENERATED    :" at 2959.22,-2109.72 h25
  text ".plot_File_Name" at 4632.23,-2109.72 h25
  text "PLOT NAME =" at 5437.73,-2109.72 h25
M9 Title Sheet:
  drawing of 63 lines, arcs and shapes, not listed
  text "1" at -72.44,15218.62 h70
  text "2" at 2423.22,15218.62 h70
  text "3" at 4912.57,15218.62 h70
  text "4" at 7419.24,15218.62 h70
  text "5" at 9918.23,15218.62 h70
  text "6" at 12423.23,15218.62 h70
  text "A" at 21915.13,5851.98 h70
  text "A" at -1224.78,5848.62 h70
  text "B" at 21915.13,3471.98 h70
  text "B" at -1224.78,3468.62 h70
  text "C" at 21915.13,1096.98 h70
  text "C" at -1224.78,1093.62 h70
  text ".PRJ_Title" at 18925.13,-897.35 h70
  text "DESIGNED FOR:" at 18875.13,-1065.02 h45
  text ".PRJ_Customer" at 18925.13,-1205.02 h70
  text "D" at 21915.13,-1273.02 h70
  text "D" at -1224.78,-1276.38 h70
  text "FILE NAME:" at 18875.13,-1365.02 h45
  text ".PCB_File_Name_No_Path" at 18925.13,-1485.02 h70
  text "Texas Instruments (TI) and/or its licensors do not warrant the accuracy or completeness of this specification" at 5565.73,-1650.22 h45
  text "ENGINEER:" at 18875.13,-1655.02 h45
  text "LAYOUT BY:" at 20380.13,-1655.02 h45
  text "or any information contained therein. TI and/or its licensors do not warrant that this design will meet" at 5520.74,-1762.89 h45
  text ".PRJ_Engineer" at 18925.13,-1810.01 h70
  text ".PCB_Layout" at 20430.63,-1810.01 h70
  text "the specifications, will be suitable for your application or fit for any particular purpose, or will operate in" at 5520.74,-1875.55 h45
  text "ALTIUM DESIGNER VERSION:" at 20380.13,-1965.02 h45
  text "an implementation. TI and/or its licensors do not warrant that the design is production worthy. You should" at 5520.74,-1988.22 h45
  text ".print_Scale" at 18925.13,-2098.35 h70
  text ".Application_BuildNumber" at 20430.63,-2098.35 h70
  text "completely validate and test your design implementation to confirm the system functionality for your application." at 5565.73,-2100.88 h45
  text "1" at -68.44,-2308.38 h70
  text "2" at 2427.22,-2308.38 h70
  text "3" at 4916.57,-2308.38 h70
  text "4" at 7423.24,-2308.38 h70
  text "5" at 9922.23,-2308.38 h70
  text "6" at 12427.23,-2308.38 h70
M10 Fab Notes:
  drawing of 245 lines, arcs and shapes, not listed
  text "IMPEDANCE TABLE:-" at 10729.94,13437.12 h60
  text "SE IMP" at 11295.94,13269.12 h50
  text "SE TRACE" at 11692.94,13266.12 h50
  text "DIFF TRACE" at 12615.94,13266.12 h50
  text "DIFF IMP" at 12168.94,13265.12 h50
  text "DIFF IMP" at 13361.94,13265.12 h50
  text "REFERENCE" at 14633.94,13202.12 h50
  text "(OHM)" at 11330.94,13181.12 h50
  text "(OHM)" at 12203.94,13177.12 h50
  text "(OHM)" at 13396.94,13177.12 h50
  text "WIDTH IN" at 11700.94,13171.12 h50
  text "WIDTH/SPACING" at 12623.94,13171.12 h50
  text "WIDTH/SPACING" at 13816.94,13171.12 h50
  text "Layer" at 10827.94,13152.12 h50
  text "+/-10%" at 11309.94,13097.12 h50
  text "Layer" at 14716.94,13095.12 h50
  text "+/-10%" at 12182.94,13093.12 h50
  text "+/-10%" at 13375.94,13093.12 h50
  text "MILS" at 11700.94,13084.12 h50
  text "IN MILS" at 12623.94,13084.12 h50
  text "IN MILS" at 13816.94,13084.12 h50
  text "50(CPW)" at 11298.94,12940.12 h50
  text "22mil" at 11728.94,12938.12 h50
  text "15mil trace/" at 12656.94,12934.12 h50
  text "12mil trace/" at 13865.94,12932.12 h50
  text "GND" at 14715.94,12925.12 h50
  text "90 ohms" at 12176.94,12890.12 h50
  text "100 ohms" at 13356.94,12888.12 h50
  text "Top Layer" at 10777.94,12881.12 h50
  text "24mil" at 11728.94,12848.12 h50
  text "7mil space" at 12656.94,12848.12 h50
  text "Layer" at 14719.94,12847.12 h50
  text "8mil space" at 13865.94,12846.12 h50
  text "50" at 11298.94,12844.12 h50
  text "5.5mil trace/" at 13871.94,12711.12 h50
  text "SIGNAL" at 10844.94,12697.12 h50
  text "GND" at 14710.94,12686.12 h50
  text "100 ohms" at 13372.94,12679.12 h50
  text "90 ohms" at 12180.94,12674.12 h50
  text "10.5 mil" at 11724.94,12670.12 h50
  text "50" at 11405.94,12665.12 h50
  text "-" at 12855.09,12643.12 h60
  text "6mil space" at 13871.94,12625.12 h50
  text "Layer1" at 10857.94,12618.12 h50
  text "Layer" at 14714.94,12608.12 h50
  text "5.5mil trace/" at 13863.94,12478.12 h50
  text "SIGNAL" at 10844.94,12470.12 h50
  text "PWR" at 14708.94,12456.12 h50
  text "10.5 mil" at 11718.94,12442.12 h50
  text "50" at 11397.94,12440.12 h50
  text "100 ohms" at 13364.94,12440.12 h50
  text "90 ohms" at 12170.94,12439.12 h50
  text "-" at 12855.09,12428.12 h60
  text "6mil space" at 13863.94,12392.12 h50
  text "Layer2" at 10857.94,12391.12 h50
  text "Layer" at 14712.94,12378.12 h50
  text "BOTTOM" at 10843.94,12244.12 h50
  text "PWR" at 14713.94,12240.12 h50
  text "4.25mil trace/" at 13808.94,12235.12 h50
  text "13.5 mil" at 11724.94,12204.12 h50
  text "90 ohms" at 12167.94,12189.12 h50
  text "100 ohms" at 13369.94,12185.12 h50
  text "-" at 12850.09,12183.12 h60
  text "50" at 11408.94,12176.12 h50
  text "Layer" at 10856.94,12165.12 h50
  text "Layer" at 14717.94,12162.12 h50
  text "4.25mil space" at 13808.94,12149.12 h50
  text "22 mil (CPW) width on top layer should be controlled 50 ohms +/- 5%" at 10642.09,11879.12 h60
  text "ALL SMA CONNECTORS TO FLUSH TO THE EDGE OF THE BOARD, NO GAP ALLOWED." at 10710.09,11750.12 h60
  text "This is especially critical for:  RFoutAP, RFoutAM, RFoutBP, and RFoutBM SMA connectors" at 10697.09,11635.12 h60
  text "DESIGN INFORMATION" at 19912.65,5768.48 h60
  text "(REFER ALSO ARRAY/PANEL PROFILING INFORMATION)" at 19551.09,5606.77 h60
  text "BOARD SIZE" at 18865.09,5602.48 h60
  text "130mm" at 20012.85,5478.48 h60
  text "X" at 19833.09,5474.66 h60
  text "175MM" at 19267.85,5468.48 h60
  text "Number of Layers :" at 19268.09,5277.48 h60
  text "6" at 20362.91,5267.48 h60
  text "MIN. TRACK WIDTH:" at 19268.09,5138.48 h60
  text "MIL" at 20519.09,5138.48 h60
  text "4.25" at 20255.85,5137.48 h60
  text "4.25" at 20240.85,5010.48 h60
  text "MIN. CLEARANCE:" at 19268.09,5006.48 h60
  text "MIL" at 20519.09,5006.48 h60
  text "16" at 20307.28,4881.98 h60
  text "MIN. VIA PAD SIZE:" at 19268.09,4874.48 h60
  text "MIL" at 20519.09,4874.48 h60
  text "5.90 MIL" at 19963.09,4732.77 h60
  text "MINIMUM ANNULAR RING" at 18938.86,4728.48 h60
  text "EXTERNAL" at 20775.85,4728.48 h60
  text "PER" at 19138.86,4610.48 h60
  text "IPC-D-275 CLASS 2 LEVEL C" at 19358.86,4610.48 h60
  text "MIL, HOLES" at 20847.09,4498.19 h60
  text "+/-" at 20454.63,4497.48 h60
  text "+/-" at 21308.63,4497.48 h60
  text "REGISTRATION TOLERANCES:" at 18938.86,4492.48 h60
  text "METAL" at 20138.63,4492.48 h60
  text "5" at 20714.84,4492.48 h60
  text "3" at 21547.84,4492.48 h60
  text "MIL" at 21664.09,4492.48 h60
  text "MATERIAL:" at 18864.09,4283.02 h60
  text "Rogers4003C and FR4 370" at 21093.28,4159.98 h30
  text "FR-4 High Tg" at 19850.54,4142.69 h60
  text "X" at 20583.28,4134.98 h60
  text "FR-408" at 19285.1,4134.12 h60
  text "OTHER" at 20773.09,4134.12 h60
  text "63 MIL (1.6mm) +/-10%" at 19605.2,3971.4 h60
  text "THICKNESS:" at 18938.86,3967.12 h60
  text "X" at 19477.03,3967.12 h60
  text "OTHER" at 20890.09,3967.12 h60
  text "TOLERANCE:" at 18938.86,3809.12 h60
  text "X" at 19778.17,3809.12 h60
  text "ANSI IPC-6012 TYPE 3 CLASS 2" at 19965.11,3809.12 h60
  text "OTHER +/-" at 19965.09,3653.12 h60
  text "BOW & TWIST:" at 18938.86,3496.12 h60
  text "X" at 19778.17,3496.12 h60
  text "ANSI IPC-6012 TYPE 3 CLASS 2" at 19965.11,3496.12 h60
  text "OTHER +/-" at 19965.09,3337.61 h60
  text "COPPER THICKNESS (FINISHED):" at 18864.09,3202.12 h60
  text "1.4MIL (1oz)" at 19744.09,3049.4 h60
  text "2MIL (1.4oz)" at 20511.09,3049.4 h60
  text "2.8MIL (2oz)" at 21238.09,3049.4 h60
  text "OUTER:" at 19221.09,3045.12 h60
  text "X" at 19615.63,3044.48 h60
  text "X" at 20385.63,2895.48 h60
  text "N/A" at 21237.63,2892.77 h60
  text "1.4MIL (1oz)" at 19744.09,2892.4 h60
  text "0.7MIL (1/2oz)" at 20511.09,2892.4 h60
  text "INNER SIGNAL:" at 18932.01,2888.12 h60
  text "X" at 19615.63,2884.48 h60
  text "DRILLING:" at 18864.09,2749.12 h60
  text "REFERENCE:" at 18938.86,2632.12 h60
  text "X" at 19587.09,2632.12 h60
  text "AS SHOWN" at 19774.09,2632.12 h60
  text "X" at 20488.09,2632.12 h60
  text "NC_DRILL FILES" at 20625.09,2632.12 h60
  text "PTH MIN COPPER THICKNESS:" at 18938.86,2474.12 h60
  text "X" at 20289.09,2474.12 h60
  text "1MIL" at 20426.09,2474.12 h60
  text "OTHER" at 20923.09,2474.12 h60
  text "BOARD FINISH:" at 18864.09,2315.12 h60
  text "SILKSCREEN:" at 19019.32,2197.12 h60
  text "X" at 19968.09,2197.12 h60
  text "TOP" at 20094.09,2197.12 h60
  text "X" at 20478.09,2197.12 h60
  text "BOTTOM" at 20605.09,2197.12 h60
  text "SILKSCREEN COLOR:" at 19019.32,2030.12 h60
  text "X" at 19967.05,2030.12 h60
  text "WHITE" at 20094.09,2030.12 h60
  text "OTHER" at 20605.09,2030.12 h60
  text "SOLDER RESIST COLOR:" at 19019.32,1860.12 h60
  text "X" at 20172.28,1707.98 h60
  text "GREEN" at 19714.09,1700.92 h60
  text "BLUE" at 20305.09,1700.92 h60
  text "OTHER" at 20843.09,1700.92 h60
  text "IMMERSION GOLD (ENIG)" at 19925.09,1512.4 h60
  text "ENEPIG" at 21262.63,1509.12 h60
  text "SURFACE FINISH:" at 18864.09,1508.12 h60
  text "X" at 19738.15,1508.12 h60
  text "IMM. TIN/SILVER OR EQUIV" at 19193.63,1351.12 h60
  text "OTHER" at 20625.09,1351.12 h60
  text "ARRAY/PANEL:" at 18864.09,1172.12 h60
  text "CUT AND TRIM PER MECH LAYER 1" at 19925.09,1167.83 h60
  text "N.C. ROUTE" at 19925.09,1016.12 h60
  text "X" at 20604.09,1016.12 h60
  text "V. SCORE" at 20791.09,1016.12 h60
  text "CERTIFICATION:" at 18864.09,879.12 h60
  text "MATERIALS AND WORKMANSHIP FOR ALL PCBS" at 19589.09,879.12 h60
  text "TO MEET OR EXCEED THE REQUIREMENTS OF:" at 19589.09,781.12 h60
  text "X" at 19215.6,644.61 h60
  text "ANSI IPC-A-600F CLASS ->" at 19354.6,644.61 h60
  text "X" at 20993.65,644.61 h60
  text "2" at 21112.6,644.62 h60
  text "1" at 20797.6,643.12 h60
  text "3" at 21466.6,643.12 h60
  text "X" at 19217.65,485.12 h60
  text "UL 94V-0" at 19354.6,485.12 h60
  text "X" at 20029.65,485.12 h60
  text "RoHS" at 20166.6,485.12 h60
  text "OTHER" at 20811,485.12 h60
  text "PER ORDER" at 21208.06,485.12 h60
  text "ADDITIONAL REQUIREMENTS:" at 18864.09,344.12 h60
  text "VIA TENTING:" at 20081.63,343.48 h60
  text "X" at 21157.28,341.98 h60
  text "YES" at 20631.3,334.4 h60
  text "NO" at 20996.11,329.17 h60
  text "MICROSECTION:" at 18938.86,229.12 h60
  text "YES" at 19844.6,229.12 h60
  text "X" at 21307.85,220.48 h60
  text "IMPEDANCE CONTROL:" at 20107.63,219.48 h60
  text "YES" at 21091.63,218.48 h60
  text "NO" at 21467.11,201.17 h60
  text "REQUIRED" at 20706.09,72.97 h60
  text "BARE BOARD ELEC. TEST:" at 18938.86,70.12 h60
  text "NONE" at 20244.6,70.12 h60
  text "X" at 20579.09,70.12 h60
  text "PER ORDER" at 21298.09,70.12 h60
  text "MANUFACTURER'S UL:" at 18938.86,-86.88 h60
  text "RAIL" at 20104.6,-91.17 h60
  text "METAL" at 20596.41,-91.17 h60
  text "SILK" at 21108.09,-91.17 h60
  text "X" at 20971.63,-91.52 h60
M11 Gerber Information:
  lines w10: -1100.28,-1975.05 5499.73,-1975.05 ; -1100.28,-1771.71 5501.73,-1771.71 ; -1100.28,-1568.38 -1100.28,-2178.38 2904.72,-2178.38 5501.73,-2178.38 5501.73,-1568.38 -1099.78,-1568.38 -1099.78,-2178.38 475.72,-2178.38 ; 1364.72,-2178.38 1364.72,-1568.38 ; 2631.72,-1771.71 2631.72,-1568.38 ; 3471.72,-1771.71 3471.72,-1568.38 ; 4093.72,-2184.88 4093.72,-1982.05
  text "E3" at 3122.95,-1695.88 h40
  text "ALL ARTWORK VIEWED FROM TOP SIDE" at -1036.78,-1700.55 h60
  text "BOARD #:" at 1439.72,-1700.55 h60
  text "'.PRJ_Number'" at 1985.22,-1700.55 h60
  text "REV:" at 2829.72,-1700.55 h60
  text "SVN REV:" at 3667.72,-1700.55 h60
  text "010131" at 1756.58,-1897.1 h60
  text "LAYER NAME =" at -1036.78,-1903.37 h60
  text "TID #:" at 1417.74,-1902.43 h60
  text "PLOT NAME =" at -1036.78,-2109.22 h60
  text ".plot_File_Name" at -231.28,-2109.22 h60
  text "GENERATED    :" at 1441.72,-2109.22 h60
  text "'.Print_Date'" at 2311.22,-2109.22 h60
  text "'.Print_Time'" at 3040.22,-2109.22 h60
  text "TEXAS INSTRUMENTS" at 4304.73,-2109.22 h60
M12 Stackup:
  drawing of 399 lines, arcs and shapes, not listed
  text "Layer" at 10678.59,11198.62 h60
  text "Name" at 11088.51,11198.62 h60
  text "Material" at 12338.15,11198.62 h60
  text "Thickness" at 13197.92,11198.62 h60
  text "Constant" at 13847.75,11198.62 h60
  text "Board Layer Stack" at 14417.61,11198.62 h60
  text "Top Overlay" at 11088.51,11078.62 h60
  text "Top Solder" at 11088.51,10958.62 h60
  text "Solder Resist" at 12338.15,10958.62 h60
  text "0.40mil" at 13197.92,10958.62 h60
  text "3.5" at 13847.75,10958.62 h60
  text "1" at 10678.59,10838.62 h60
  text "Layer 1 - Top Layer" at 11088.51,10838.62 h60
  text "1.40mil" at 13197.92,10838.62 h60
  text "Dielectric 1" at 11088.51,10718.62 h60
  text "Rogers4003C" at 12338.15,10718.62 h60
  text "12.00mil" at 13197.92,10718.62 h60
  text "4.2" at 13847.75,10718.62 h60
  text "2" at 10678.59,10598.62 h60
  text "Layer 2 - GND Layer" at 11088.51,10598.62 h60
  text "1.40mil" at 13197.92,10598.62 h60
  text "Dielectric 2" at 11088.51,10478.62 h60
  text "FR4 370" at 12338.15,10478.62 h60
  text "8.50mil" at 13197.92,10478.62 h60
  text "4.2" at 13847.75,10478.62 h60
  text "3" at 10678.59,10358.62 h60
  text "Layer 3 - Signal" at 11088.51,10358.62 h60
  text "1.40mil" at 13197.92,10358.62 h60
  text "Dielectric 3" at 11088.51,10238.62 h60
  text "FR4 370" at 12338.15,10238.62 h60
  text "14.50mil" at 13197.92,10238.62 h60
  text "4.2" at 13847.75,10238.62 h60
  text "4" at 10678.59,10118.62 h60
  text "Layer 4 - Signal" at 11088.51,10118.62 h60
  text "1.40mil" at 13197.92,10118.62 h60
  text "Dielectric 4" at 11088.51,9998.62 h60
  text "FR4 370" at 12338.15,9998.62 h60
  text "8.50mil" at 13197.92,9998.62 h60
  text "4.2" at 13847.75,9998.62 h60
  text "5" at 10678.59,9878.62 h60
  text "Layer 5 - GND" at 11088.51,9878.62 h60
  text "1.40mil" at 13197.92,9878.62 h60
  text "Dielectric 5" at 11088.51,9758.62 h60
  text "FR4 370" at 12338.15,9758.62 h60
  text "8.00mil" at 13197.92,9758.62 h60
  text "4.2" at 13847.75,9758.62 h60
  text "6" at 10678.59,9638.62 h60
  text "Bottom Layer" at 11088.51,9638.62 h60
  text "1.40mil" at 13197.92,9638.62 h60
  text "Bottom Solder" at 11088.51,9518.62 h60
  text "Solder Resist" at 12338.15,9518.62 h60
  text "0.40mil" at 13197.92,9518.62 h60
  text "3.5" at 13847.75,9518.62 h60
  text "Bottom Overlay" at 11088.51,9398.62 h60
M13 Component Bodies Top:
  text ".Layer_Name" at -231.28,-1903.37 h60
M14 Component Bodies Bottom:
  text ".Layer_Name" at -231.28,-1903.37 h60
M15 Courtyards Top:
  text ".Layer_Name" at -231.28,-1903.37 h60
M16 Courtyards Bottom:
  text ".Layer_Name" at -231.28,-1903.37 h60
